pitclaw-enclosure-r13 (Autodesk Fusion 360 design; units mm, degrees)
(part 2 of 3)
extrude "Extrude7" new body sketch "J2 contact 4 profile" blind 0.12 from offset 11.78 bodies "J2 contact 4"
sketch "J2 contact 5 profile" plane through (0, 0, 0) normal (0, 0, 1) x axis (1, 0, 0)
  line L1 (21.115, 49.05) -> (20.845, 49.05)
  line L2 (21.155, 51.51) -> (21.155, 49.09)
  line L3 (20.845, 51.55) -> (21.115, 51.55)
  line L4 (20.805, 49.09) -> (20.805, 51.51)
  arc A1 centre (21.115, 49.09) radius 0.04 clockwise from (21.155, 49.09) to (21.115, 49.05)
  arc A2 centre (21.115, 51.51) radius 0.04 clockwise from (21.115, 51.55) to (21.155, 51.51)
  arc A3 centre (20.845, 51.51) radius 0.04 clockwise from (20.805, 51.51) to (20.845, 51.55)
  arc A4 centre (20.845, 49.09) radius 0.04 clockwise from (20.845, 49.05) to (20.805, 49.09)
extrude "Extrude8" new body sketch "J2 contact 5 profile" blind 0.12 from offset 11.78 bodies "J2 contact 5"
sketch "J2 contact 6 profile" plane through (0, 0, 0) normal (0, 0, 1) x axis (1, 0, 0)
  line L1 (22.135, 49.05) -> (21.865, 49.05)
  line L2 (22.175, 51.51) -> (22.175, 49.09)
  line L3 (21.865, 51.55) -> (22.135, 51.55)
  line L4 (21.825, 49.09) -> (21.825, 51.51)
  arc A1 centre (22.135, 49.09) radius 0.04 clockwise from (22.175, 49.09) to (22.135, 49.05)
  arc A2 centre (22.135, 51.51) radius 0.04 clockwise from (22.135, 51.55) to (22.175, 51.51)
  arc A3 centre (21.865, 51.51) radius 0.04 clockwise from (21.825, 51.51) to (21.865, 51.55)
  arc A4 centre (21.865, 49.09) radius 0.04 clockwise from (21.865, 49.05) to (21.825, 49.09)
extrude "Extrude9" new body sketch "J2 contact 6 profile" blind 0.12 from offset 11.78 bodies "J2 contact 6"
sketch "J2 contact 7 profile" plane through (0, 0, 0) normal (0, 0, 1) x axis (1, 0, 0)
  line L1 (23.155, 49.05) -> (22.885, 49.05)
  line L2 (23.195, 51.51) -> (23.195, 49.09)
  line L3 (22.885, 51.55) -> (23.155, 51.55)
  line L4 (22.845, 49.09) -> (22.845, 51.51)
  arc A1 centre (23.155, 49.09) radius 0.04 clockwise from (23.195, 49.09) to (23.155, 49.05)
  arc A2 centre (23.155, 51.51) radius 0.04 clockwise from (23.155, 51.55) to (23.195, 51.51)
  arc A3 centre (22.885, 51.51) radius 0.04 clockwise from (22.845, 51.51) to (22.885, 51.55)
  arc A4 centre (22.885, 49.09) radius 0.04 clockwise from (22.885, 49.05) to (22.845, 49.09)
extrude "Extrude10" new body sketch "J2 contact 7 profile" blind 0.12 from offset 11.78 bodies "J2 contact 7"
sketch "J2 contact 8 profile" plane through (0, 0, 0) normal (0, 0, 1) x axis (1, 0, 0)
  line L1 (24.175, 49.05) -> (23.905, 49.05)
  line L2 (24.215, 51.51) -> (24.215, 49.09)
  line L3 (23.905, 51.55) -> (24.175, 51.55)
  line L4 (23.865, 49.09) -> (23.865, 51.51)
  arc A1 centre (24.175, 49.09) radius 0.04 clockwise from (24.215, 49.09) to (24.175, 49.05)
  arc A2 centre (24.175, 51.51) radius 0.04 clockwise from (24.175, 51.55) to (24.215, 51.51)
  arc A3 centre (23.905, 51.51) radius 0.04 clockwise from (23.865, 51.51) to (23.905, 51.55)
  arc A4 centre (23.905, 49.09) radius 0.04 clockwise from (23.905, 49.05) to (23.865, 49.09)
extrude "Extrude11" new body sketch "J2 contact 8 profile" blind 0.12 from offset 11.78 bodies "J2 contact 8"
sketch "J2 leads profile" plane through (0, 0, 0) normal (0, 0, 1) x axis (1, 0, 0)
  circle C1 centre (16.94, 44.38) radius 0.275
  circle C2 centre (17.956, 42.6) radius 0.275
  circle C3 centre (18.972, 44.38) radius 0.275
  circle C4 centre (19.988, 42.6) radius 0.275
  circle C5 centre (21.004, 44.38) radius 0.275
  circle C6 centre (22.02, 42.6) radius 0.275
  circle C7 centre (23.036, 44.38) radius 0.275
  circle C8 centre (24.052, 42.6) radius 0.275
extrude "Extrude12" new body sketch "J2 leads profile" blind 3.5 from offset 6.5 bodies "J2 leads", "J2 leads (1)", "J2 leads (2)", "J2 leads (3)", "J2 leads (4)", "J2 leads (5)", "J2 leads (6)", "J2 leads (7)"
sketch "J9 barrel housing profile" plane through (0, 0, 0) normal (0, 0, 1) x axis (1, 0, 0)
  line L1 (7.85, 37.6) -> (-0.85, 37.6)
  line L2 (8, 51.85) -> (8, 37.75)
  line L3 (-0.85, 52) -> (7.85, 52)
  line L4 (-1, 37.75) -> (-1, 51.85)
  arc A1 centre (7.85, 37.75) radius 0.15 clockwise from (8, 37.75) to (7.85, 37.6)
  arc A2 centre (7.85, 51.85) radius 0.15 clockwise from (7.85, 52) to (8, 51.85)
  arc A3 centre (-0.85, 51.85) radius 0.15 clockwise from (-1, 51.85) to (-0.85, 52)
  arc A4 centre (-0.85, 37.75) radius 0.15 clockwise from (-0.85, 37.6) to (-1, 37.75)
extrude "Extrude1" new body sketch "J9 barrel housing profile" blind 10.8 from offset 9.1 bodies "J9 barrel housing"
sketch "J9 barrel opening profile" plane through (0, 0, 0) normal (0, 1, 0) x axis (1, 0, 0)
  circle C1 centre (3.5, -15.6) radius 3.15
extrude "Extrude2" cut sketch "J9 barrel opening profile" blind 3.55 from offset 48.5
sketch "J9 center pin profile" plane through (0, 0, 0) normal (0, 1, 0) x axis (1, 0, 0)
  circle C1 centre (3.5, -15.6) radius 1.05
extrude "Extrude3" new body sketch "J9 center pin profile" blind 2.6 from offset 49 bodies "J9 center pin"
sketch "J9 leads profile" plane through (0, 0, 0) normal (0, 0, 1) x axis (1, 0, 0)
  circle C1 centre (3.5, 38.4) radius 0.325
  circle C2 centre (3.5, 44.3) radius 0.325
  circle C3 centre (-1.2, 41.2) radius 0.325
extrude "Extrude4" new body sketch "J9 leads profile" blind 3.5 from offset 6.5 bodies "J9 leads", "J9 leads (1)", "J9 leads (2)"
sketch "J4 jack housing profile" plane through (0, 0, 0) normal (0, 0, 1) x axis (1, 0, 0)
  line L1 (19.4, -41.5) -> (14.6, -41.5)
  line L2 (19.55, -33.65) -> (19.55, -41.35)
  line L3 (14.6, -33.5) -> (19.4, -33.5)
  line L4 (14.45, -41.35) -> (14.45, -33.65)
  arc A1 centre (19.4, -41.35) radius 0.15 clockwise from (19.55, -41.35) to (19.4, -41.5)
  arc A2 centre (19.4, -33.65) radius 0.15 clockwise from (19.4, -33.5) to (19.55, -33.65)
  arc A3 centre (14.6, -33.65) radius 0.15 clockwise from (14.45, -33.65) to (14.6, -33.5)
  arc A4 centre (14.6, -41.35) radius 0.15 clockwise from (14.6, -41.5) to (14.45, -41.35)
extrude "Extrude1" new body sketch "J4 jack housing profile" blind 5.1 from offset 9.1 bodies "J4 jack housing"
sketch "J4 front collar profile" plane through (0, 0, 0) normal (0, 1, 0) x axis (1, 0, 0)
  circle C1 centre (17, -11.65) radius 2
extrude "Extrude2" new body sketch "J4 front collar profile" blind 3.1 from offset -44.5 bodies "J4 front collar"
sketch "J4 2.5mm plug bore profile" plane through (0, 0, 0) normal (0, 1, 0) x axis (1, 0, 0)
  circle C1 centre (17, -11.65) radius 1.25
extrude "Extrude3" cut sketch "J4 2.5mm plug bore profile" blind 3.3 from offset -44.52
sketch "J4 leads profile" plane through (0, 0, 0) normal (0, 0, 1) x axis (1, 0, 0)
  circle C1 centre (17, -33.4) radius 0.275
  circle C2 centre (18.8, -35.5) radius 0.275
  circle C3 centre (15.2, -35.5) radius 0.275
extrude "Extrude4" new body sketch "J4 leads profile" blind 3.5 from offset 6.5 bodies "J4 leads", "J4 leads (1)", "J4 leads (2)"
sketch "J5 jack housing profile" plane through (0, 0, 0) normal (0, 0, 1) x axis (1, 0, 0)
  line L1 (2.4, -41.5) -> (-2.4, -41.5)
  line L2 (2.55, -33.65) -> (2.55, -41.35)
  line L3 (-2.4, -33.5) -> (2.4, -33.5)
  line L4 (-2.55, -41.35) -> (-2.55, -33.65)
  arc A1 centre (2.4, -41.35) radius 0.15 clockwise from (2.55, -41.35) to (2.4, -41.5)
  arc A2 centre (2.4, -33.65) radius 0.15 clockwise from (2.4, -33.5) to (2.55, -33.65)
  arc A3 centre (-2.4, -33.65) radius 0.15 clockwise from (-2.55, -33.65) to (-2.4, -33.5)
  arc A4 centre (-2.4, -41.35) radius 0.15 clockwise from (-2.4, -41.5) to (-2.55, -41.35)
extrude "Extrude1" new body sketch "J5 jack housing profile" blind 5.1 from offset 9.1 bodies "J5 jack housing"
sketch "J5 front collar profile" plane through (0, 0, 0) normal (0, 1, 0) x axis (1, 0, 0)
  circle C1 centre (0, -11.65) radius 2
extrude "Extrude2" new body sketch "J5 front collar profile" blind 3.1 from offset -44.5 bodies "J5 front collar"
sketch "J5 2.5mm plug bore profile" plane through (0, 0, 0) normal (0, 1, 0) x axis (1, 0, 0)
  circle C1 centre (0, -11.65) radius 1.25
extrude "Extrude3" cut sketch "J5 2.5mm plug bore profile" blind 3.3 from offset -44.52
sketch "J5 leads profile" plane through (0, 0, 0) normal (0, 0, 1) x axis (1, 0, 0)
  circle C1 centre (0, -33.4) radius 0.275
  circle C2 centre (1.8, -35.5) radius 0.275
  circle C3 centre (-1.8, -35.5) radius 0.275
extrude "Extrude4" new body sketch "J5 leads profile" blind 3.5 from offset 6.5 bodies "J5 leads", "J5 leads (1)", "J5 leads (2)"
sketch "J6 jack housing profile" plane through (0, 0, 0) normal (0, 0, 1) x axis (1, 0, 0)
  line L1 (-14.6, -41.5) -> (-19.4, -41.5)
  line L2 (-14.45, -33.65) -> (-14.45, -41.35)
  line L3 (-19.4, -33.5) -> (-14.6, -33.5)
  line L4 (-19.55, -41.35) -> (-19.55, -33.65)
  arc A1 centre (-14.6, -41.35) radius 0.15 clockwise from (-14.45, -41.35) to (-14.6, -41.5)
  arc A2 centre (-14.6, -33.65) radius 0.15 clockwise from (-14.6, -33.5) to (-14.45, -33.65)
  arc A3 centre (-19.4, -33.65) radius 0.15 clockwise from (-19.55, -33.65) to (-19.4, -33.5)
  arc A4 centre (-19.4, -41.35) radius 0.15 clockwise from (-19.4, -41.5) to (-19.55, -41.35)
extrude "Extrude1" new body sketch "J6 jack housing profile" blind 5.1 from offset 9.1 bodies "J6 jack housing"
sketch "J6 front collar profile" plane through (0, 0, 0) normal (0, 1, 0) x axis (1, 0, 0)
  circle C1 centre (-17, -11.65) radius 2
extrude "Extrude2" new body sketch "J6 front collar profile" blind 3.1 from offset -44.5 bodies "J6 front collar"
sketch "J6 2.5mm plug bore profile" plane through (0, 0, 0) normal (0, 1, 0) x axis (1, 0, 0)
  circle C1 centre (-17, -11.65) radius 1.25
extrude "Extrude3" cut sketch "J6 2.5mm plug bore profile" blind 3.3 from offset -44.52
sketch "J6 leads profile" plane through (0, 0, 0) normal (0, 0, 1) x axis (1, 0, 0)
  circle C1 centre (-17, -33.4) radius 0.275
  circle C2 centre (-15.2, -35.5) radius 0.275
  circle C3 centre (-18.8, -35.5) radius 0.275
extrude "Extrude4" new body sketch "J6 leads profile" blind 3.5 from offset 6.5 bodies "J6 leads", "J6 leads (1)", "J6 leads (2)"
sketch "J8 female socket profile" plane through (0, 0, 0) normal (0, 0, 1) x axis (1, 0, 0)
  line L1 (18.12, -9.77) -> (-6.98, -9.77)
  line L2 (18.27, -7.38) -> (18.27, -9.62)
  line L3 (-6.98, -7.23) -> (18.12, -7.23)
  line L4 (-7.13, -9.62) -> (-7.13, -7.38)
  arc A1 centre (18.12, -9.62) radius 0.15 clockwise from (18.27, -9.62) to (18.12, -9.77)
  arc A2 centre (18.12, -7.38) radius 0.15 clockwise from (18.12, -7.23) to (18.27, -7.38)
  arc A3 centre (-6.98, -7.38) radius 0.15 clockwise from (-7.13, -7.38) to (-6.98, -7.23)
  arc A4 centre (-6.98, -9.62) radius 0.15 clockwise from (-6.98, -9.77) to (-7.13, -9.62)
extrude "Extrude1" new body sketch "J8 female socket profile" blind 8.5 from offset 9.1 bodies "J8 female socket"
sketch "J8 socket receptacles profile" plane through (0, 0, 0) normal (0, 0, 1) x axis (1, 0, 0)
  circle C1 centre (17, -8.5) radius 0.575
  circle C2 centre (14.46, -8.5) radius 0.575
  circle C3 centre (11.92, -8.5) radius 0.575
  circle C4 centre (9.38, -8.5) radius 0.575
  circle C5 centre (6.84, -8.5) radius 0.575
  circle C6 centre (4.3, -8.5) radius 0.575
  circle C7 centre (1.76, -8.5) radius 0.575
  circle C8 centre (-0.78, -8.5) radius 0.575
  circle C9 centre (-3.32, -8.5) radius 0.575
  circle C10 centre (-5.86, -8.5) radius 0.575
extrude "Extrude2" cut sketch "J8 socket receptacles profile" blind 0.82 from offset 16.8
sketch "ADS1115 blue module PCB profile" plane through (0, 0, 0) normal (0, 0, 1) x axis (1, 0, 0)
  line L1 (19.24, -24) -> (-8.16, -24)
  line L2 (19.54, -7.3) -> (19.54, -23.7)
  line L3 (-8.16, -7) -> (19.24, -7)
  line L4 (-8.46, -23.7) -> (-8.46, -7.3)
  arc A1 centre (19.24, -23.7) radius 0.3 clockwise from (19.54, -23.7) to (19.24, -24)
  arc A2 centre (19.24, -7.3) radius 0.3 clockwise from (19.24, -7) to (19.54, -7.3)
  arc A3 centre (-8.16, -7.3) radius 0.3 clockwise from (-8.46, -7.3) to (-8.16, -7)
  arc A4 centre (-8.16, -23.7) radius 0.3 clockwise from (-8.16, -24) to (-8.46, -23.7)
extrude "Extrude3" new body sketch "ADS1115 blue module PCB profile" blind 1.6 from offset 17.6 bodies "ADS1115 blue module PCB"
sketch "ADS1115 IC visual body profile" plane through (0, 0, 0) normal (0, 0, 1) x axis (1, 0, 0)
  line L1 (7.92, -19.5) -> (3.16, -19.5)
  line L2 (8.04, -15.62) -> (8.04, -19.38)
  line L3 (3.16, -15.5) -> (7.92, -15.5)
  line L4 (3.04, -19.38) -> (3.04, -15.62)
  arc A1 centre (7.92, -19.38) radius 0.12 clockwise from (8.04, -19.38) to (7.92, -19.5)
  arc A2 centre (7.92, -15.62) radius 0.12 clockwise from (7.92, -15.5) to (8.04, -15.62)
  arc A3 centre (3.16, -15.62) radius 0.12 clockwise from (3.04, -15.62) to (3.16, -15.5)
  arc A4 centre (3.16, -19.38) radius 0.12 clockwise from (3.16, -19.5) to (3.04, -19.38)
extrude "Extrude4" new body sketch "ADS1115 IC visual body profile" blind 1.2 from offset 19.2 bodies "ADS1115 IC visual body"
sketch "ADC header pin profile" plane through (0, 0, 0) normal (0, 0, 1) x axis (1, 0, 0)
  circle C1 centre (17, -8.5) radius 0.32
extrude "Extrude5" new body sketch "ADC header pin profile" blind 12.5 from offset 7 bodies "ADC header pin"
sketch "ADC header pin profile (1)" plane through (0, 0, 0) normal (0, 0, 1) x axis (1, 0, 0)
  circle C1 centre (14.46, -8.5) radius 0.32
extrude "Extrude6" new body sketch "ADC header pin profile (1)" blind 12.5 from offset 7 bodies "ADC header pin (1)"
sketch "ADC header pin profile (2)" plane through (0, 0, 0) normal (0, 0, 1) x axis (1, 0, 0)
  circle C1 centre (11.92, -8.5) radius 0.32
extrude "Extrude7" new body sketch "ADC header pin profile (2)" blind 12.5 from offset 7 bodies "ADC header pin (2)"
sketch "ADC header pin profile (3)" plane through (0, 0, 0) normal (0, 0, 1) x axis (1, 0, 0)
  circle C1 centre (9.38, -8.5) radius 0.32
extrude "Extrude8" new body sketch "ADC header pin profile (3)" blind 12.5 from offset 7 bodies "ADC header pin (3)"
sketch "ADC header pin profile (4)" plane through (0, 0, 0) normal (0, 0, 1) x axis (1, 0, 0)
  circle C1 centre (6.84, -8.5) radius 0.32
extrude "Extrude9" new body sketch "ADC header pin profile (4)" blind 12.5 from offset 7 bodies "ADC header pin (4)"
sketch "ADC header pin profile (5)" plane through (0, 0, 0) normal (0, 0, 1) x axis (1, 0, 0)
  circle C1 centre (4.3, -8.5) radius 0.32
extrude "Extrude10" new body sketch "ADC header pin profile (5)" blind 12.5 from offset 7 bodies "ADC header pin (5)"
sketch "ADC header pin profile (6)" plane through (0, 0, 0) normal (0, 0, 1) x axis (1, 0, 0)
  circle C1 centre (1.76, -8.5) radius 0.32
extrude "Extrude11" new body sketch "ADC header pin profile (6)" blind 12.5 from offset 7 bodies "ADC header pin (6)"
sketch "ADC header pin profile (7)" plane through (0, 0, 0) normal (0, 0, 1) x axis (1, 0, 0)
  circle C1 centre (-0.78, -8.5) radius 0.32
extrude "Extrude12" new body sketch "ADC header pin profile (7)" blind 12.5 from offset 7 bodies "ADC header pin (7)"
sketch "ADC header pin profile (8)" plane through (0, 0, 0) normal (0, 0, 1) x axis (1, 0, 0)
  circle C1 centre (-3.32, -8.5) radius 0.32
extrude "Extrude13" new body sketch "ADC header pin profile (8)" blind 12.5 from offset 7 bodies "ADC header pin (8)"
sketch "ADC header pin profile (9)" plane through (0, 0, 0) normal (0, 0, 1) x axis (1, 0, 0)
  circle C1 centre (-5.86, -8.5) radius 0.32
extrude "Extrude14" new body sketch "ADC header pin profile (9)" blind 12.5 from offset 7 bodies "ADC header pin (9)"
sketch "Adafruit5807 PCB profile" plane through (0, 0, 0) normal (0, 0, 1) x axis (1, 0, 0)
  line L1 (-4.54, 25.362) -> (-24.46, 25.362)
  line L2 (-4.34, 48.657) -> (-4.34, 25.562)
  line L3 (-24.46, 48.857) -> (-4.54, 48.857)
  line L4 (-24.66, 25.562) -> (-24.66, 48.657)
  arc A1 centre (-4.54, 25.562) radius 0.2 clockwise from (-4.34, 25.562) to (-4.54, 25.362)
  arc A2 centre (-4.54, 48.657) radius 0.2 clockwise from (-4.54, 48.857) to (-4.34, 48.657)
  arc A3 centre (-24.46, 48.657) radius 0.2 clockwise from (-24.66, 48.657) to (-24.46, 48.857)
  arc A4 centre (-24.46, 25.562) radius 0.2 clockwise from (-24.46, 25.362) to (-24.66, 25.562)
extrude "Extrude1" new body sketch "Adafruit5807 PCB profile" blind 1.6 from offset 12.1 bodies "Adafruit5807 PCB"
sketch "5807 M2 mounting holes profile" plane through (0, 0, 0) normal (0, 0, 1) x axis (1, 0, 0)
  circle C1 centre (-6.753, 46.317) radius 1.25
  circle C2 centre (-21.993, 46.317) radius 1.25
extrude "Extrude2" cut sketch "5807 M2 mounting holes profile" blind 1.64 from offset 12.08
sketch "3mm nylon spacer profile" plane through (0, 0, 0) normal (0, 0, 1) x axis (1, 0, 0)
  circle C1 centre (-6.753, 46.317) radius 2.5
extrude "Extrude3" new body sketch "3mm nylon spacer profile" blind 3 from offset 9.1 bodies "3mm nylon spacer"
sketch "M2 head washer profile" plane through (0, 0, 0) normal (0, 0, 1) x axis (1, 0, 0)
  circle C1 centre (-6.753, 46.317) radius 2.5
extrude "Extrude4" new body sketch "M2 head washer profile" blind 0.3 from offset 13.7 bodies "M2 head washer"
sketch "M2 screw head profile" plane through (0, 0, 0) normal (0, 0, 1) x axis (1, 0, 0)
  circle C1 centre (-6.753, 46.317) radius 2
extrude "Extrude5" new body sketch "M2 screw head profile" blind 1.5 from offset 14 bodies "M2 screw head"
sketch "3mm nylon spacer profile (1)" plane through (0, 0, 0) normal (0, 0, 1) x axis (1, 0, 0)
  circle C1 centre (-21.993, 46.317) radius 2.5
extrude "Extrude6" new body sketch "3mm nylon spacer profile (1)" blind 3 from offset 9.1 bodies "3mm nylon spacer (1)"
sketch "M2 head washer profile (1)" plane through (0, 0, 0) normal (0, 0, 1) x axis (1, 0, 0)
  circle C1 centre (-21.993, 46.317) radius 2.5
extrude "Extrude7" new body sketch "M2 head washer profile (1)" blind 0.3 from offset 13.7 bodies "M2 head washer (1)"
sketch "M2 screw head profile (1)" plane through (0, 0, 0) normal (0, 0, 1) x axis (1, 0, 0)
  circle C1 centre (-21.993, 46.317) radius 2
extrude "Extrude8" new body sketch "M2 screw head profile (1)" blind 1.5 from offset 14 bodies "M2 screw head (1)"
sketch "USB-C metal shell profile" plane through (0, 0, 0) normal (0, 1, 0) x axis (1, 0, 0)
  line L1 (-11.23, -13.6) -> (-17.77, -13.6)
  line L2 (-10.03, -15.6) -> (-10.03, -14.8)
  line L3 (-17.77, -16.8) -> (-11.23, -16.8)
  line L4 (-18.97, -14.8) -> (-18.97, -15.6)
  arc A1 centre (-11.23, -14.8) radius 1.2 clockwise from (-11.23, -13.6) to (-10.03, -14.8)
  arc A2 centre (-11.23, -15.6) radius 1.2 clockwise from (-10.03, -15.6) to (-11.23, -16.8)
  arc A3 centre (-17.77, -15.6) radius 1.2 clockwise from (-17.77, -16.8) to (-18.97, -15.6)
  arc A4 centre (-17.77, -14.8) radius 1.2 clockwise from (-18.97, -14.8) to (-17.77, -13.6)
extrude "Extrude9" new body sketch "USB-C metal shell profile" blind 7.5 from offset 42.5 bodies "USB-C metal shell"
sketch "USB-C mouth profile" plane through (0, 0, 0) normal (0, 1, 0) x axis (1, 0, 0)
  line L1 (-11.65, -14.2) -> (-17.35, -14.2)
  line L2 (-10.75, -15.3) -> (-10.75, -15.1)
  line L3 (-17.35, -16.2) -> (-11.65, -16.2)
  line L4 (-18.25, -15.1) -> (-18.25, -15.3)
  arc A1 centre (-11.65, -15.1) radius 0.9 clockwise from (-11.65, -14.2) to (-10.75, -15.1)
  arc A2 centre (-11.65, -15.3) radius 0.9 clockwise from (-10.75, -15.3) to (-11.65, -16.2)
  arc A3 centre (-17.35, -15.3) radius 0.9 clockwise from (-17.35, -16.2) to (-18.25, -15.3)
  arc A4 centre (-17.35, -15.1) radius 0.9 clockwise from (-18.25, -15.1) to (-17.35, -14.2)
extrude "Extrude10" cut sketch "USB-C mouth profile" blind 2.02 from offset 48
sketch "USB-C inner tongue profile" plane through (0, 0, 0) normal (0, 0, 1) x axis (1, 0, 0)
  line L1 (-11.52, 48.1) -> (-17.48, 48.1)
  line L2 (-11.4, 49.78) -> (-11.4, 48.22)
  line L3 (-17.48, 49.9) -> (-11.52, 49.9)
  line L4 (-17.6, 48.22) -> (-17.6, 49.78)
  arc A1 centre (-11.52, 48.22) radius 0.12 clockwise from (-11.4, 48.22) to (-11.52, 48.1)
  arc A2 centre (-11.52, 49.78) radius 0.12 clockwise from (-11.52, 49.9) to (-11.4, 49.78)
  arc A3 centre (-17.48, 49.78) radius 0.12 clockwise from (-17.6, 49.78) to (-17.48, 49.9)
  arc A4 centre (-17.48, 48.22) radius 0.12 clockwise from (-17.48, 48.1) to (-17.6, 48.22)
extrude "Extrude11" new body sketch "USB-C inner tongue profile" blind 0.5 from offset 14.95 bodies "USB-C inner tongue"
position "Position1"
sketch "Probe recess backing profile" plane through (0, 0, 0) normal (0, 1, 0) x axis (1, 0, 0)
  line L1 (28, -1.65) -> (-28, -1.65)
  line L2 (32, -17.65) -> (32, -5.65)
  line L3 (-28, -21.65) -> (28, -21.65)
  line L4 (-32, -5.65) -> (-32, -17.65)
  arc A1 centre (28, -5.65) radius 4 clockwise from (28, -1.65) to (32, -5.65)
  arc A2 centre (28, -17.65) radius 4 clockwise from (32, -17.65) to (28, -21.65)
  arc A3 centre (-28, -17.65) radius 4 clockwise from (-28, -21.65) to (-32, -17.65)
  arc A4 centre (-28, -5.65) radius 4 clockwise from (-32, -5.65) to (-28, -1.65)
extrude "Extrude18" add sketch "Probe recess backing profile" blind 9.5 from offset -52
work_plane "WorkPlane1" AlongDistance -52.02 ExtraOffset 0
sketch "Outer lip with cable clearance profile" plane through (0, -52.02, 0) normal (0, 1, 0) x axis (1, 0, 0)
  line L1 (24.5, -1.65) -> (-24.5, -1.65)
  line L2 (30, -15.15) -> (30, -7.15)
  line L3 (-24.5, -20.65) -> (24.5, -20.65)
  line L4 (-30, -7.15) -> (-30, -15.15)
  arc A1 centre (24.5, -7.15) radius 5.5 clockwise from (24.5, -1.65) to (30, -7.15)
  arc A2 centre (24.5, -15.15) radius 5.5 clockwise from (30, -15.15) to (24.5, -20.65)
  arc A3 centre (-24.5, -15.15) radius 5.5 clockwise from (-24.5, -20.65) to (-30, -15.15)
  arc A4 centre (-24.5, -7.15) radius 5.5 clockwise from (-30, -7.15) to (-24.5, -1.65)
work_plane "WorkPlane2" AlongDistance -44.5 ExtraOffset 0
sketch "Probe pocket floor profile" plane through (0, -44.5, 0) normal (0, 1, 0) x axis (1, 0, 0)
  line L1 (22, -5.65) -> (-22, -5.65)
  line L2 (25, -14.65) -> (25, -8.65)
  line L3 (-22, -17.65) -> (22, -17.65)
  line L4 (-25, -8.65) -> (-25, -14.65)
  arc A1 centre (22, -8.65) radius 3 clockwise from (22, -5.65) to (25, -8.65)
  arc A2 centre (22, -14.65) radius 3 clockwise from (25, -14.65) to (22, -17.65)
  arc A3 centre (-22, -14.65) radius 3 clockwise from (-22, -17.65) to (-25, -14.65)
  arc A4 centre (-22, -8.65) radius 3 clockwise from (-25, -8.65) to (-22, -5.65)
loft "Loft1" sketch "Outer lip with cable clearance profile" + "Probe pocket floor profile"
copy_paste_bodies "CopyPasteBodies1"
sketch "Fascia boundary profile" plane through (0, 0, 0) normal (0, 0, 1) x axis (1, 0, 0)
  line L1 (33, -53) -> (-33, -53)
  line L2 (33, -42.5) -> (33, -53)
  line L3 (-33, -42.5) -> (33, -42.5)
  line L4 (-33, -53) -> (-33, -42.5)
extrude "Extrude1" sketch "Fascia boundary profile" along normal blind 27.3
sketch "Open probe end for carrier installation profile" plane through (0, 0, 0) normal (0, 0, 1) x axis (1, 0, 0)
  line L1 (33.3, -53) -> (-33.3, -53)
  line L2 (33.3, -42) -> (33.3, -53)
  line L3 (-33.3, -42) -> (33.3, -42)
  line L4 (-33.3, -53) -> (-33.3, -42)
extrude "Extrude19" cut sketch "Open probe end for carrier installation profile" blind 27.64 from offset -0.02
sketch "Open guide block -1 profile" plane through (0, 0, 0) normal (0, 0, 1) x axis (1, 0, 0)
  line L1 (-33.3, -52) -> (-39, -52)
  line L2 (-33.3, -40.5) -> (-33.3, -52)
  line L3 (-39, -40.5) -> (-33.3, -40.5)
  line L4 (-39, -52) -> (-39, -40.5)
extrude "Extrude20" add sketch "Open guide block -1 profile" along normal blind 8
sketch "Open guide block 1 profile" plane through (0, 0, 0) normal (0, 0, 1) x axis (1, 0, 0)
  line L1 (39, -52) -> (33.3, -52)
  line L2 (39, -40.5) -> (39, -52)
  line L3 (33.3, -40.5) -> (39, -40.5)
  line L4 (33.3, -52) -> (33.3, -40.5)
extrude "Extrude21" add sketch "Open guide block 1 profile" along normal blind 8
sketch "Original rounded case perimeter profile" plane through (0, 0, 0) normal (0, 0, 1) x axis (1, 0, 0)
  line L1 (38, -52) -> (-38, -52)
  line L2 (43, 47) -> (43, -47)
  line L3 (-38, 52) -> (38, 52)
  line L4 (-43, -47) -> (-43, 47)
  arc A1 centre (38, -47) radius 5 clockwise from (43, -47) to (38, -52)
  arc A2 centre (38, 47) radius 5 clockwise from (38, 52) to (43, 47)
  arc A3 centre (-38, 47) radius 5 clockwise from (-43, 47) to (-38, 52)
  arc A4 centre (-38, -47) radius 5 clockwise from (-38, -52) to (-43, -47)
extrude "Extrude22" sketch "Original rounded case perimeter profile" along normal blind 27.6
sketch "Open-top guide channel -1 profile" plane through (0, 0, 0) normal (0, 0, 1) x axis (1, 0, 0)
  line L1 (-32.7, -52.1) -> (-36.3, -52.1)
  line L2 (-32.7, -43) -> (-32.7, -52.1)
  line L3 (-36.3, -43) -> (-32.7, -43)
  line L4 (-36.3, -52.1) -> (-36.3, -43)
extrude "Extrude23" cut sketch "Open-top guide channel -1 profile" blind 4.3 from offset 3.8
sketch "Fascia side web -1 profile" plane through (0, 0, 0) normal (0, 0, 1) x axis (1, 0, 0)
  line L1 (-31, -52) -> (-33, -52)
  line L2 (-31, -42.5) -> (-31, -52)
  line L3 (-33, -42.5) -> (-31, -42.5)
  line L4 (-33, -52) -> (-33, -42.5)
extrude "Extrude2" add sketch "Fascia side web -1 profile" blind 5.52 from offset 2.48
sketch "Sliding runner -1 profile" plane through (0, 0, 0) normal (0, 0, 1) x axis (1, 0, 0)
  line L1 (-32.7, -52) -> (-36, -52)
  line L2 (-32.7, -43) -> (-32.7, -52)
  line L3 (-36, -43) -> (-32.7, -43)
  line L4 (-36, -52) -> (-36, -43)
extrude "Extrude3" add sketch "Sliding runner -1 profile" blind 2 from offset 3.8
sketch "Guide entry cover -1 profile" plane through (0, 0, 0) normal (0, 0, 1) x axis (1, 0, 0)
  line L1 (-32.7, -52) -> (-36, -52)
  line L2 (-32.7, -50.7) -> (-32.7, -52)
  line L3 (-36, -50.7) -> (-32.7, -50.7)
  line L4 (-36, -52) -> (-36, -50.7)
extrude "Extrude4" add sketch "Guide entry cover -1 profile" blind 2 from offset 5.8
sketch "Keeper support web -1 profile" plane through (0, 0, 0) normal (0, 0, 1) x axis (1, 0, 0)
  line L1 (-29, -49.5) -> (-31.3, -49.5)
  line L2 (-29, -45.5) -> (-29, -49.5)
  line L3 (-31.3, -45.5) -> (-29, -45.5)
  line L4 (-31.3, -49.5) -> (-31.3, -45.5)
extrude "Extrude5" add sketch "Keeper support web -1 profile" blind 7 from offset 18
sketch "Open-top guide channel 1 profile" plane through (0, 0, 0) normal (0, 0, 1) x axis (1, 0, 0)
  line L1 (36.3, -52.1) -> (32.7, -52.1)
  line L2 (36.3, -43) -> (36.3, -52.1)
  line L3 (32.7, -43) -> (36.3, -43)
  line L4 (32.7, -52.1) -> (32.7, -43)
extrude "Extrude24" cut sketch "Open-top guide channel 1 profile" blind 4.3 from offset 3.8
sketch "Fascia side web 1 profile" plane through (0, 0, 0) normal (0, 0, 1) x axis (1, 0, 0)
  line L1 (33, -52) -> (31, -52)
  line L2 (33, -42.5) -> (33, -52)
  line L3 (31, -42.5) -> (33, -42.5)
  line L4 (31, -52) -> (31, -42.5)
extrude "Extrude6" add sketch "Fascia side web 1 profile" blind 5.52 from offset 2.48
sketch "Sliding runner 1 profile" plane through (0, 0, 0) normal (0, 0, 1) x axis (1, 0, 0)
  line L1 (36, -52) -> (32.7, -52)
  line L2 (36, -43) -> (36, -52)
  line L3 (32.7, -43) -> (36, -43)
  line L4 (32.7, -52) -> (32.7, -43)
extrude "Extrude7" add sketch "Sliding runner 1 profile" blind 2 from offset 3.8
sketch "Guide entry cover 1 profile" plane through (0, 0, 0) normal (0, 0, 1) x axis (1, 0, 0)
  line L1 (36, -52) -> (32.7, -52)
  line L2 (36, -50.7) -> (36, -52)
  line L3 (32.7, -50.7) -> (36, -50.7)
  line L4 (32.7, -52) -> (32.7, -50.7)
extrude "Extrude8" add sketch "Guide entry cover 1 profile" blind 2 from offset 5.8
sketch "Keeper support web 1 profile" plane through (0, 0, 0) normal (0, 0, 1) x axis (1, 0, 0)
  line L1 (31.3, -49.5) -> (29, -49.5)
  line L2 (31.3, -45.5) -> (31.3, -49.5)
  line L3 (29, -45.5) -> (31.3, -45.5)
  line L4 (29, -49.5) -> (29, -45.5)
extrude "Extrude9" add sketch "Keeper support web 1 profile" blind 7 from offset 18
sketch "Reinforced keeper block -21 profile" plane through (0, 0, 0) normal (0, 0, 1) x axis (1, 0, 0)
  line L1 (-11.7, -52) -> (-30.3, -52)
  line L2 (-11.7, -45.5) -> (-11.7, -52)
  line L3 (-30.3, -45.5) -> (-11.7, -45.5)
  line L4 (-30.3, -52) -> (-30.3, -45.5)
extrude "Extrude10" add sketch "Reinforced keeper block -21 profile" blind 4.2 from offset 20.8
sketch "Open keeper notch -21 profile" plane through (0, 0, 0) normal (0, 0, 1) x axis (1, 0, 0)
  line L1 (-14.7, -50.85) -> (-27.3, -50.85)
  line L2 (-14.7, -48.25) -> (-14.7, -50.85)
  line L3 (-27.3, -48.25) -> (-14.7, -48.25)
  line L4 (-27.3, -50.85) -> (-27.3, -48.25)
extrude "Extrude11" cut sketch "Open keeper notch -21 profile" blind 6.54 from offset 20.78
sketch "Reinforced keeper block 21 profile" plane through (0, 0, 0) normal (0, 0, 1) x axis (1, 0, 0)
  line L1 (30.3, -52) -> (11.7, -52)
  line L2 (30.3, -45.5) -> (30.3, -52)
  line L3 (11.7, -45.5) -> (30.3, -45.5)
  line L4 (11.7, -52) -> (11.7, -45.5)
extrude "Extrude12" add sketch "Reinforced keeper block 21 profile" blind 4.2 from offset 20.8
sketch "Open keeper notch 21 profile" plane through (0, 0, 0) normal (0, 0, 1) x axis (1, 0, 0)
  line L1 (27.3, -50.85) -> (14.7, -50.85)
  line L2 (27.3, -48.25) -> (27.3, -50.85)
  line L3 (14.7, -48.25) -> (27.3, -48.25)
  line L4 (14.7, -50.85) -> (14.7, -48.25)
extrude "Extrude13" cut sketch "Open keeper notch 21 profile" blind 6.54 from offset 20.78
sketch "Three probe clearance bores profile" plane through (0, 0, 0) normal (0, 1, 0) x axis (1, 0, 0)
  circle C1 centre (-17, -11.65) radius 2.8
  circle C2 centre (0, -11.65) radius 2.8
  circle C3 centre (17, -11.65) radius 2.8
extrude "Extrude14" cut sketch "Three probe clearance bores profile" blind 2.04 from offset -44.52
work_plane "WorkPlane1" AlongDistance -43.1 ExtraOffset 0
sketch "Probe-17 lead-in inner profile" plane through (0, -43.1, 0) normal (0, 1, 0) x axis (1, 0, 0)
  circle C1 centre (-17, -11.65) radius 2.8
work_plane "WorkPlane2" AlongDistance -42.48 ExtraOffset 0
sketch "Probe-17 lead-in rear profile" plane through (0, -42.48, 0) normal (0, 1, 0) x axis (1, 0, 0)
  circle C1 centre (-17, -11.65) radius 3.2
loft "Loft1" sketch "Probe-17 lead-in inner profile" + "Probe-17 lead-in rear profile"
work_plane "WorkPlane3" AlongDistance -43.1 ExtraOffset 0
sketch "Probe0 lead-in inner profile" plane through (0, -43.1, 0) normal (0, 1, 0) x axis (1, 0, 0)
  circle C1 centre (0, -11.65) radius 2.8
work_plane "WorkPlane4" AlongDistance -42.48 ExtraOffset 0
sketch "Probe0 lead-in rear profile" plane through (0, -42.48, 0) normal (0, 1, 0) x axis (1, 0, 0)
  circle C1 centre (0, -11.65) radius 3.2
loft "Loft2" sketch "Probe0 lead-in inner profile" + "Probe0 lead-in rear profile"
work_plane "WorkPlane5" AlongDistance -43.1 ExtraOffset 0
sketch "Probe17 lead-in inner profile" plane through (0, -43.1, 0) normal (0, 1, 0) x axis (1, 0, 0)
  circle C1 centre (17, -11.65) radius 2.8
work_plane "WorkPlane6" AlongDistance -42.48 ExtraOffset 0
sketch "Probe17 lead-in rear profile" plane through (0, -42.48, 0) normal (0, 1, 0) x axis (1, 0, 0)
  circle C1 centre (17, -11.65) radius 3.2
loft "Loft3" sketch "Probe17 lead-in inner profile" + "Probe17 lead-in rear profile"
sketch "Keeper root web -21 profile" plane through (0, 0, 0) normal (0, 0, 1) x axis (1, 0, 0)
  line L1 (-15, -51.5) -> (-27, -51.5)
  line L2 (-15, -48.5) -> (-15, -51.5)
  line L3 (-27, -48.5) -> (-15, -48.5)
  line L4 (-27, -51.5) -> (-27, -48.5)
extrude "Extrude15" add sketch "Keeper root web -21 profile" blind 2 from offset 27.6
sketch "Wide fascia key -21 profile" plane through (0, 0, 0) normal (0, 0, 1) x axis (1, 0, 0)
  line L1 (-15, -50.6) -> (-27, -50.6)
  line L2 (-15, -48.5) -> (-15, -50.6)
  line L3 (-27, -48.5) -> (-15, -48.5)
  line L4 (-27, -50.6) -> (-27, -48.5)
extrude "Extrude16" add sketch "Wide fascia key -21 profile" blind 5.2 from offset 23.4
work_plane "WorkPlane3" AlongDistance 23 ExtraOffset 0
sketch "Key -21 entry tip profile" plane through (0, 0, 23) normal (0, 0, 1) x axis (1, 0, 0)
  line L1 (-15.4, -50.2) -> (-26.6, -50.2)
  line L2 (-15.4, -48.9) -> (-15.4, -50.2)
  line L3 (-26.6, -48.9) -> (-15.4, -48.9)
  line L4 (-26.6, -50.2) -> (-26.6, -48.9)
work_plane "WorkPlane4" AlongDistance 23.4 ExtraOffset 0
sketch "Key -21 entry full section profile" plane through (0, 0, 23.4) normal (0, 0, 1) x axis (1, 0, 0)
  line L1 (-15, -50.6) -> (-27, -50.6)
  line L2 (-15, -48.5) -> (-15, -50.6)
  line L3 (-27, -48.5) -> (-15, -48.5)
  line L4 (-27, -50.6) -> (-27, -48.5)
loft "Loft2" sketch "Key -21 entry tip profile" + "Key -21 entry full section profile"
sketch "Keeper root web 21 profile" plane through (0, 0, 0) normal (0, 0, 1) x axis (1, 0, 0)
  line L1 (27, -51.5) -> (15, -51.5)
  line L2 (27, -48.5) -> (27, -51.5)
  line L3 (15, -48.5) -> (27, -48.5)
  line L4 (15, -51.5) -> (15, -48.5)
extrude "Extrude17" add sketch "Keeper root web 21 profile" blind 2 from offset 27.6
sketch "Wide fascia key 21 profile" plane through (0, 0, 0) normal (0, 0, 1) x axis (1, 0, 0)
  line L1 (27, -50.6) -> (15, -50.6)
  line L2 (27, -48.5) -> (27, -50.6)
  line L3 (15, -48.5) -> (27, -48.5)
  line L4 (15, -50.6) -> (15, -48.5)
extrude "Extrude18" add sketch "Wide fascia key 21 profile" blind 5.2 from offset 23.4
work_plane "WorkPlane5" AlongDistance 23 ExtraOffset 0
sketch "Key 21 entry tip profile" plane through (0, 0, 23) normal (0, 0, 1) x axis (1, 0, 0)
  line L1 (26.6, -50.2) -> (15.4, -50.2)
  line L2 (26.6, -48.9) -> (26.6, -50.2)
  line L3 (15.4, -48.9) -> (26.6, -48.9)
  line L4 (15.4, -50.2) -> (15.4, -48.9)
work_plane "WorkPlane6" AlongDistance 23.4 ExtraOffset 0
sketch "Key 21 entry full section profile" plane through (0, 0, 23.4) normal (0, 0, 1) x axis (1, 0, 0)
  line L1 (27, -50.6) -> (15, -50.6)
  line L2 (27, -48.5) -> (27, -50.6)
  line L3 (15, -48.5) -> (27, -48.5)
  line L4 (15, -50.6) -> (15, -48.5)
loft "Loft3" sketch "Key 21 entry tip profile" + "Key 21 entry full section profile"
sketch "Four internal accessory mounting bosses profile" plane through (0, 0, 0) normal (0, 0, 1) x axis (1, 0, 0)
  circle C1 centre (-36, -37) radius 5
  circle C2 centre (-36, 37) radius 5
  circle C3 centre (36, -37) radius 5
  circle C4 centre (36, 37) radius 5
extrude "Extrude25" add sketch "Four internal accessory mounting bosses profile" blind 5 from offset 2.5
sketch "Mount to wall and closure web -1 -1 profile" plane through (0, 0, 0) normal (0, 0, 1) x axis (1, 0, 0)
  line L1 (-35, -37) -> (-40.7, -37)
  line L2 (-35, -28) -> (-35, -37)
  line L3 (-40.7, -28) -> (-35, -28)
  line L4 (-40.7, -37) -> (-40.7, -28)
extrude "Extrude26" add sketch "Mount to wall and closure web -1 -1 profile" blind 5 from offset 2.5
sketch "Mount to wall and closure web -1 1 profile" plane through (0, 0, 0) normal (0, 0, 1) x axis (1, 0, 0)
  line L1 (-35, 28) -> (-40.7, 28)
  line L2 (-35, 37) -> (-35, 28)
  line L3 (-40.7, 37) -> (-35, 37)
  line L4 (-40.7, 28) -> (-40.7, 37)
extrude "Extrude27" add sketch "Mount to wall and closure web -1 1 profile" blind 5 from offset 2.5
sketch "Mount to wall and closure web 1 -1 profile" plane through (0, 0, 0) normal (0, 0, 1) x axis (1, 0, 0)
  line L1 (40.7, -37) -> (35, -37)
  line L2 (40.7, -28) -> (40.7, -37)
  line L3 (35, -28) -> (40.7, -28)
  line L4 (35, -37) -> (35, -28)
extrude "Extrude28" add sketch "Mount to wall and closure web 1 -1 profile" blind 5 from offset 2.5
sketch "Mount to wall and closure web 1 1 profile" plane through (0, 0, 0) normal (0, 0, 1) x axis (1, 0, 0)
  line L1 (40.7, 28) -> (35, 28)
  line L2 (40.7, 37) -> (40.7, 28)
  line L3 (35, 37) -> (40.7, 37)
  line L4 (35, 28) -> (35, 37)
extrude "Extrude29" add sketch "Mount to wall and closure web 1 1 profile" blind 5 from offset 2.5
sketch "Inside entry M3 insert pilots profile" plane through (0, 0, 0) normal (0, 0, 1) x axis (1, 0, 0)
  circle C1 centre (-36, -37) radius 2.1
  circle C2 centre (-36, 37) radius 2.1
  circle C3 centre (36, -37) radius 2.1
  circle C4 centre (36, 37) radius 2.1
extrude "Extrude30" cut sketch "Inside entry M3 insert pilots profile" blind 5.02 from offset 2.5
sketch "External M3 screw access profile" plane through (0, 0, 0) normal (0, 0, 1) x axis (1, 0, 0)
  circle C1 centre (-36, -37) radius 1.7
  circle C2 centre (-36, 37) radius 1.7
  circle C3 centre (36, -37) radius 1.7
  circle C4 centre (36, 37) radius 1.7
extrude "Extrude31" cut sketch "External M3 screw access profile" blind 2.54 from offset -0.02
sketch "Four short M3 insert envelopes profile" plane through (0, 0, 0) normal (0, 0, 1) x axis (1, 0, 0)
  circle C1 centre (-36, -37) radius 2.5
  circle C2 centre (-36, 37) radius 2.5
  circle C3 centre (36, -37) radius 2.5
  circle C4 centre (36, 37) radius 2.5
extrude "Extrude1" new body sketch "Four short M3 insert envelopes profile" blind 4 from offset 3.5 bodies "M3Sx4 mounting insert - simplified reference", "M3Sx4 mounting insert - simplified reference (1)", "M3Sx4 mounting insert - simplified reference (2)", "M3Sx4 mounting insert - simplified reference (3)"
sketch "Nominal thread minor bores - simplified profile" plane through (0, 0, 0) normal (0, 0, 1) x axis (1, 0, 0)
  circle C1 centre (-36, -37) radius 1.25
  circle C2 centre (-36, 37) radius 1.25
  circle C3 centre (36, -37) radius 1.25
  circle C4 centre (36, 37) radius 1.25
extrude "Extrude2" cut sketch "Nominal thread minor bores - simplified profile" blind 4.04 from offset 3.48
sketch "Heat tool clearance over probe guide stop -1 profile" plane through (0, 0, 0) normal (0, 0, 1) x axis (1, 0, 0)
  line L1 (-33.3, -43) -> (-39, -43)
  line L2 (-33.3, -40.5) -> (-33.3, -43)
  line L3 (-39, -40.5) -> (-33.3, -40.5)
  line L4 (-39, -43) -> (-39, -40.5)
extrude "Extrude32" cut sketch "Heat tool clearance over probe guide stop -1 profile" blind 0.52 from offset 7.5
sketch "Heat tool clearance over probe guide stop 1 profile" plane through (0, 0, 0) normal (0, 0, 1) x axis (1, 0, 0)
  line L1 (39, -43) -> (33.3, -43)
  line L2 (39, -40.5) -> (39, -43)
  line L3 (33.3, -40.5) -> (39, -40.5)
  line L4 (33.3, -43) -> (33.3, -40.5)
extrude "Extrude33" cut sketch "Heat tool clearance over probe guide stop 1 profile" blind 0.52 from offset 7.5
sketch "Remove stepped runner and front cover -1 profile" plane through (0, 0, 0) normal (0, 0, 1) x axis (1, 0, 0)
  line L1 (-32.95, -52.02) -> (-36.02, -52.02)
  line L2 (-32.95, -42.99) -> (-32.95, -52.02)
  line L3 (-36.02, -42.99) -> (-32.95, -42.99)
  line L4 (-36.02, -52.02) -> (-36.02, -42.99)
extrude "Extrude15" cut sketch "Remove stepped runner and front cover -1 profile" blind 4.01 from offset 3.8
sketch "Continuous runner root web -1 profile" plane through (0, 0, 0) normal (0, 0, 1) x axis (1, 0, 0)
  line L1 (-31, -52) -> (-33, -52)
  line L2 (-31, -42.5) -> (-31, -52)
  line L3 (-33, -42.5) -> (-31, -42.5)
  line L4 (-33, -52) -> (-33, -42.5)
extrude "Extrude16" add sketch "Continuous runner root web -1 profile" blind 7.02 from offset 2.48
sketch "Constant full-depth runner -1 profile" plane through (0, 0, 0) normal (0, 1, 0) x axis (1, 0, 0)
  line L1 (-36, -3.8) -> (-32.7, -3.8)
  line L2 (-36, -5.8) -> (-36, -3.8)
  line L3 (-32.7, -9.1) -> (-36, -5.8)
  line L4 (-32.7, -3.8) -> (-32.7, -9.1)
extrude "Extrude17" add sketch "Constant full-depth runner -1 profile" blind 9 from offset -52
sketch "Continuous guide roof blank -1 profile" plane through (0, 0, 0) normal (0, 0, 1) x axis (1, 0, 0)
  line L1 (-33.3, -52) -> (-39, -52)
  line L2 (-33.3, -43) -> (-33.3, -52)
  line L3 (-39, -43) -> (-33.3, -43)
  line L4 (-39, -52) -> (-39, -43)
extrude "Extrude34" add sketch "Continuous guide roof blank -1 profile" blind 6.8 from offset 3.8
sketch "Remove stepped runner and front cover 1 profile" plane through (0, 0, 0) normal (0, 0, 1) x axis (1, 0, 0)
  line L1 (36.02, -52.02) -> (32.95, -52.02)
  line L2 (36.02, -42.99) -> (36.02, -52.02)
  line L3 (32.95, -42.99) -> (36.02, -42.99)
  line L4 (32.95, -52.02) -> (32.95, -42.99)
extrude "Extrude18" cut sketch "Remove stepped runner and front cover 1 profile" blind 4.01 from offset 3.8
sketch "Continuous runner root web 1 profile" plane through (0, 0, 0) normal (0, 0, 1) x axis (1, 0, 0)
  line L1 (33, -52) -> (31, -52)
  line L2 (33, -42.5) -> (33, -52)
  line L3 (31, -42.5) -> (33, -42.5)
  line L4 (31, -52) -> (31, -42.5)
extrude "Extrude19" add sketch "Continuous runner root web 1 profile" blind 7.02 from offset 2.48
sketch "Constant full-depth runner 1 profile" plane through (0, 0, 0) normal (0, 1, 0) x axis (1, 0, 0)
  line L1 (36, -3.8) -> (32.7, -3.8)
  line L2 (36, -5.8) -> (36, -3.8)
  line L3 (32.7, -9.1) -> (36, -5.8)
  line L4 (32.7, -3.8) -> (32.7, -9.1)
extrude "Extrude20" add sketch "Constant full-depth runner 1 profile" blind 9 from offset -52
sketch "Continuous guide roof blank 1 profile" plane through (0, 0, 0) normal (0, 0, 1) x axis (1, 0, 0)
  line L1 (39, -52) -> (33.3, -52)
  line L2 (39, -43) -> (39, -52)
  line L3 (33.3, -43) -> (39, -43)
  line L4 (33.3, -52) -> (33.3, -43)
extrude "Extrude35" add sketch "Continuous guide roof blank 1 profile" blind 6.8 from offset 3.8
sketch "Preserve original rounded exterior profile" plane through (0, 0, 0) normal (0, 0, 1) x axis (1, 0, 0)
  line L1 (38, -52) -> (-38, -52)
  line L2 (43, 47) -> (43, -47)
  line L3 (-38, 52) -> (38, 52)
  line L4 (-43, -47) -> (-43, 47)
  arc A1 centre (38, -47) radius 5 clockwise from (43, -47) to (38, -52)
  arc A2 centre (38, 47) radius 5 clockwise from (38, 52) to (43, 47)
  arc A3 centre (-38, 47) radius 5 clockwise from (-43, 47) to (-38, 52)
  arc A4 centre (-38, -47) radius 5 clockwise from (-38, -52) to (-43, -47)
extrude "Extrude36" sketch "Preserve original rounded exterior profile" along normal blind 27.6
sketch "Constant full-depth guide cavity -1 profile" plane through (0, 0, 0) normal (0, 1, 0) x axis (1, 0, 0)
  line L1 (-36.4, -3.8) -> (-32.7, -3.8)
  line L2 (-36.4, -5.9) -> (-36.4, -3.8)
  line L3 (-32.7, -9.6) -> (-36.4, -5.9)
  line L4 (-32.7, -3.8) -> (-32.7, -9.6)
extrude "Extrude37" cut sketch "Constant full-depth guide cavity -1 profile" blind 9.1 from offset -52.1
sketch "Constant full-depth guide cavity 1 profile" plane through (0, 0, 0) normal (0, 1, 0) x axis (1, 0, 0)
  line L1 (36.4, -3.8) -> (32.7, -3.8)
  line L2 (36.4, -5.9) -> (36.4, -3.8)
  line L3 (32.7, -9.6) -> (36.4, -5.9)
  line L4 (32.7, -3.8) -> (32.7, -9.6)
extrude "Extrude38" cut sketch "Constant full-depth guide cavity 1 profile" blind 9.1 from offset -52.1
sketch "Guide receiver refill -1 profile" plane through (0, 0, 0) normal (0, 0, 1) x axis (1, 0, 0)
  line L1 (-33.3, -52) -> (-39, -52)
  line L2 (-33.3, -43) -> (-33.3, -52)
  line L3 (-39, -43) -> (-33.3, -43)
  line L4 (-39, -52) -> (-39, -43)
extrude "Extrude39" add sketch "Guide receiver refill -1 profile" blind 6.9 from offset 3.7
sketch "Guide receiver refill 1 profile" plane through (0, 0, 0) normal (0, 0, 1) x axis (1, 0, 0)
  line L1 (39, -52) -> (33.3, -52)
  line L2 (39, -43) -> (39, -52)
  line L3 (33.3, -43) -> (39, -43)
  line L4 (33.3, -52) -> (33.3, -43)
extrude "Extrude40" add sketch "Guide receiver refill 1 profile" blind 6.9 from offset 3.7
sketch "Preserve rounded case outline profile" plane through (0, 0, 0) normal (0, 0, 1) x axis (1, 0, 0)
  line L1 (38, -52) -> (-38, -52)
  line L2 (43, 47) -> (43, -47)
  line L3 (-38, 52) -> (38, 52)
  line L4 (-43, -47) -> (-43, 47)
  arc A1 centre (38, -47) radius 5 clockwise from (43, -47) to (38, -52)
  arc A2 centre (38, 47) radius 5 clockwise from (38, 52) to (43, 47)
  arc A3 centre (-38, 47) radius 5 clockwise from (-43, 47) to (-38, 52)
  arc A4 centre (-38, -47) radius 5 clockwise from (-38, -52) to (-43, -47)
extrude "Extrude41" sketch "Preserve rounded case outline profile" along normal blind 27.6
sketch "Guide side and roof clearance -1 profile" plane through (0, 0, 0) normal (0, 1, 0) x axis (1, 0, 0)
  line L1 (-36.3, -3.8) -> (-32.7, -3.8)
  line L2 (-36.3, -6.0657) -> (-36.3, -3.8)
  line L3 (-32.7, -9.6657) -> (-36.3, -6.0657)
  line L4 (-32.7, -3.8) -> (-32.7, -9.6657)
extrude "Extrude42" cut sketch "Guide side and roof clearance -1 profile" blind 9.1 from offset -52.1
sketch "Two guide seating lands -1 profile" plane through (0, 0, 0) normal (1, 0, 0) x axis (0, 0, -1)
  line L1 (-3.5, -50.6) -> (-3.5, -52.1)
  line L2 (-3.8, -50) -> (-3.5, -50.6)
  line L3 (-3.8, -49.2) -> (-3.8, -50)
  line L4 (-3.5, -48.6) -> (-3.8, -49.2)
  line L5 (-3.5, -44.6) -> (-3.5, -48.6)
  line L6 (-3.8, -44) -> (-3.5, -44.6)
  line L7 (-3.8, -43) -> (-3.8, -44)
  line L8 (-3.82, -43) -> (-3.8, -43)
  line L9 (-3.82, -52.1) -> (-3.82, -43)
  line L10 (-3.5, -52.1) -> (-3.82, -52.1)
extrude "Extrude43" cut sketch "Two guide seating lands -1 profile" blind 3.6 from offset -36.3
sketch "Guide side and roof clearance 1 profile" plane through (0, 0, 0) normal (0, 1, 0) x axis (1, 0, 0)
  line L1 (36.3, -3.8) -> (32.7, -3.8)
  line L2 (36.3, -6.0657) -> (36.3, -3.8)
  line L3 (32.7, -9.6657) -> (36.3, -6.0657)
  line L4 (32.7, -3.8) -> (32.7, -9.6657)
extrude "Extrude44" cut sketch "Guide side and roof clearance 1 profile" blind 9.1 from offset -52.1
sketch "Two guide seating lands 1 profile" plane through (0, 0, 0) normal (1, 0, 0) x axis (0, 0, -1)
  line L1 (-3.5, -50.6) -> (-3.5, -52.1)
  line L2 (-3.8, -50) -> (-3.5, -50.6)
  line L3 (-3.8, -49.2) -> (-3.8, -50)
  line L4 (-3.5, -48.6) -> (-3.8, -49.2)
  line L5 (-3.5, -44.6) -> (-3.5, -48.6)
  line L6 (-3.8, -44) -> (-3.5, -44.6)
  line L7 (-3.8, -43) -> (-3.8, -44)
  line L8 (-3.82, -43) -> (-3.8, -43)
  line L9 (-3.82, -52.1) -> (-3.82, -43)
  line L10 (-3.5, -52.1) -> (-3.82, -52.1)
extrude "Extrude45" cut sketch "Two guide seating lands 1 profile" blind 3.6 from offset 32.7
sketch "Fascia side seam adjustment -1 profile" plane through (0, 0, 0) normal (0, 0, 1) x axis (1, 0, 0)
  line L1 (-33, -52) -> (-33.1, -52)
  line L2 (-33, -49.5) -> (-33, -52)
  line L3 (-33.1, -49.5) -> (-33, -49.5)
  line L4 (-33.1, -52) -> (-33.1, -49.5)
extrude "Extrude21" add sketch "Fascia side seam adjustment -1 profile" along normal blind 27.4
sketch "Fascia full root web width -1 profile" plane through (0, 0, 0) normal (0, 0, 1) x axis (1, 0, 0)
  line L1 (-31, -52) -> (-33.1, -52)
  line L2 (-31, -42.5) -> (-31, -52)
  line L3 (-33.1, -42.5) -> (-31, -42.5)
  line L4 (-33.1, -52) -> (-33.1, -42.5)
extrude "Extrude22" add sketch "Fascia full root web width -1 profile" blind 7.02 from offset 2.48
sketch "Fascia floor side seam adjustment -1 profile" plane through (0, 0, 0) normal (0, 0, 1) x axis (1, 0, 0)
  line L1 (-33, -52) -> (-33.1, -52)
  line L2 (-33, -42.5) -> (-33, -52)
  line L3 (-33.1, -42.5) -> (-33, -42.5)
  line L4 (-33.1, -52) -> (-33.1, -42.5)
extrude "Extrude23" add sketch "Fascia floor side seam adjustment -1 profile" along normal blind 2.5
sketch "Fascia side seam adjustment 1 profile" plane through (0, 0, 0) normal (0, 0, 1) x axis (1, 0, 0)
  line L1 (33.1, -52) -> (33, -52)
  line L2 (33.1, -49.5) -> (33.1, -52)
  line L3 (33, -49.5) -> (33.1, -49.5)
  line L4 (33, -52) -> (33, -49.5)
extrude "Extrude24" add sketch "Fascia side seam adjustment 1 profile" along normal blind 27.4
sketch "Fascia full root web width 1 profile" plane through (0, 0, 0) normal (0, 0, 1) x axis (1, 0, 0)
  line L1 (33.1, -52) -> (31, -52)
  line L2 (33.1, -42.5) -> (33.1, -52)
  line L3 (31, -42.5) -> (33.1, -42.5)
  line L4 (31, -52) -> (31, -42.5)
extrude "Extrude25" add sketch "Fascia full root web width 1 profile" blind 7.02 from offset 2.48
sketch "Fascia floor side seam adjustment 1 profile" plane through (0, 0, 0) normal (0, 0, 1) x axis (1, 0, 0)
  line L1 (33.1, -52) -> (33, -52)
  line L2 (33.1, -42.5) -> (33.1, -52)
  line L3 (33, -42.5) -> (33.1, -42.5)
  line L4 (33, -52) -> (33, -42.5)
extrude "Extrude26" add sketch "Fascia floor side seam adjustment 1 profile" along normal blind 2.5
sketch "Fascia top seam adjustment profile" plane through (0, 0, 0) normal (0, 0, 1) x axis (1, 0, 0)
  line L1 (33.1, -52) -> (-33.1, -52)
  line L2 (33.1, -49.5) -> (33.1, -52)
  line L3 (-33.1, -49.5) -> (33.1, -49.5)
  line L4 (-33.1, -52) -> (-33.1, -49.5)
extrude "Extrude27" add sketch "Fascia top seam adjustment profile" blind 0.1 from offset 27.3
sketch "Fascia floor rear joint adjustment profile" plane through (0, 0, 0) normal (0, 0, 1) x axis (1, 0, 0)
  line L1 (33.1, -42.52) -> (-33.1, -42.52)
  line L2 (33.1, -42.2) -> (33.1, -42.52)
  line L3 (-33.1, -42.2) -> (33.1, -42.2)
  line L4 (-33.1, -42.52) -> (-33.1, -42.2)
extrude "Extrude28" add sketch "Fascia floor rear joint adjustment profile" along normal blind 2.5
sketch "Keep keeper notch open through top -21 profile" plane through (0, 0, 0) normal (0, 0, 1) x axis (1, 0, 0)
  line L1 (-14.7, -50.85) -> (-27.3, -50.85)
  line L2 (-14.7, -48.25) -> (-14.7, -50.85)
  line L3 (-27.3, -48.25) -> (-14.7, -48.25)
  line L4 (-27.3, -50.85) -> (-27.3, -48.25)
extrude "Extrude29" cut sketch "Keep keeper notch open through top -21 profile" blind 6.64 from offset 20.78
sketch "Keep keeper notch open through top 21 profile" plane through (0, 0, 0) normal (0, 0, 1) x axis (1, 0, 0)
  line L1 (27.3, -50.85) -> (14.7, -50.85)
  line L2 (27.3, -48.25) -> (27.3, -50.85)
  line L3 (14.7, -48.25) -> (27.3, -48.25)
  line L4 (14.7, -50.85) -> (14.7, -48.25)
extrude "Extrude30" cut sketch "Keep keeper notch open through top 21 profile" blind 6.64 from offset 20.78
